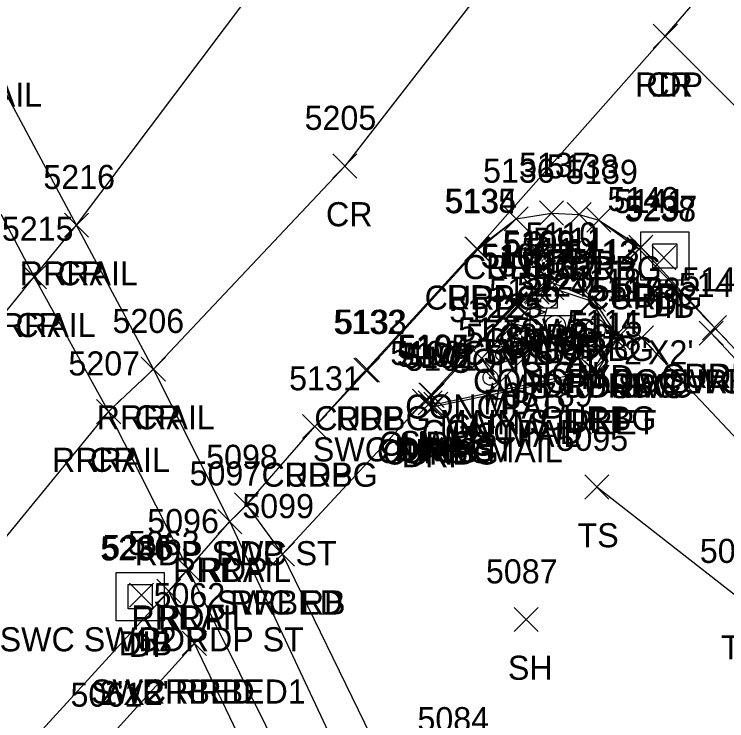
# Model space of a CAD drawing. Extents: x 1618146 to 1620418, y 640749 to 641927.
# Drawn here: x 1620288.8 to 1620347.9, y 640931.1 to 640989.8 of the extents above; entities that cross this region are included whole.
import ezdxf

# ---------------------------------------------------------------- set-up
doc = ezdxf.new("R2010")
doc.units = 0
for name, color, linetype in [('D_A', 7, 'Continuous'), ('D_C', 7, 'Continuous'), ('D_I', 7, 'Continuous'), ('D_TIC', 7, 'Continuous'), ('DS', 7, 'Continuous'), ('L_A', 7, 'Continuous'), ('L_C', 7, 'Continuous'), ('L_I', 7, 'Continuous'), ('L_TIC', 7, 'Continuous'), ('LELB', 7, 'Continuous'), ('LMB', 7, 'Continuous'), ('LS', 7, 'Continuous'), ('P_A', 7, 'Continuous'), ('P_I', 7, 'Continuous'), ('P_TIC', 7, 'Continuous'), ('PET', 7, 'Continuous'), ('PRC', 7, 'Continuous'), ('R_A', 7, 'Continuous'), ('R_I', 7, 'Continuous'), ('R_TIC', 7, 'Continuous'), ('RC', 7, 'Continuous'), ('RDP', 7, 'Continuous'), ('RR', 7, 'Continuous'), ('RRB', 7, 'Continuous'), ('RSW', 7, 'Continuous'), ('S_A', 7, 'Continuous'), ('S_C', 7, 'Continuous'), ('S_I', 7, 'Continuous'), ('SSGN', 7, 'Continuous'), ('U_A', 7, 'Continuous'), ('U_C', 7, 'Continuous'), ('U_I', 7, 'Continuous'), ('UP', 7, 'Continuous'), ('UPGW', 7, 'Continuous'), ('UWFH', 7, 'Continuous')]:
    doc.layers.add(name, color=color, linetype=linetype)

msp = doc.modelspace()

# ---------------------------------------------------------------- linework, layer by layer
at = {"layer": 'D_TIC'}
for points in [[(1620341.709, 640968.564), (1620343.709, 640970.564)], [(1620343.709, 640968.564), (1620341.709, 640970.564)], [(1620298.337, 640940.546), (1620300.337, 640942.546)], [(1620300.337, 640940.546), (1620298.337, 640942.546)]]:
    msp.add_lwpolyline(points, dxfattribs=at)
at = {"layer": 'DS'}
for p, q in [((1620340.801, 640971.698), (1620344.801, 640971.698)), ((1620340.801, 640967.698), (1620340.801, 640971.698)), ((1620344.801, 640971.698), (1620344.801, 640967.698)), ((1620341.801, 640968.698), (1620341.801, 640970.698)), ((1620341.801, 640970.698), (1620343.801, 640970.698)), ((1620343.801, 640970.698), (1620343.801, 640968.698)), ((1620342.806, 640969.699), (1620342.806, 640969.699)), ((1620342.806, 640969.699), (1620342.806, 640969.699)), ((1620343.801, 640968.698), (1620341.801, 640968.698)), ((1620344.801, 640967.698), (1620340.801, 640967.698)), ((1620297.224, 640943.429), (1620301.224, 640943.429)), ((1620297.224, 640939.429), (1620297.224, 640943.429)), ((1620301.224, 640943.429), (1620301.224, 640939.429)), ((1620298.224, 640940.429), (1620298.224, 640942.429)), ((1620298.224, 640942.429), (1620300.224, 640942.429)), ((1620300.224, 640942.429), (1620300.224, 640940.429)), ((1620299.229, 640941.431), (1620299.229, 640941.431)), ((1620299.229, 640941.431), (1620299.229, 640941.431)), ((1620300.224, 640940.429), (1620298.224, 640940.429)), ((1620301.224, 640939.429), (1620297.224, 640939.429))]:
    msp.add_line(p, q, dxfattribs=at)
at = {"layer": 'L_TIC'}
for points in [[(1620330.186, 640964), (1620332.186, 640966)], [(1620332.186, 640964), (1620330.186, 640966)], [(1620330.186, 640964), (1620332.186, 640966)], [(1620332.186, 640964), (1620330.186, 640966)], [(1620332.227, 640962.328), (1620334.227, 640964.328)], [(1620334.227, 640962.328), (1620332.227, 640964.328)], [(1620332.227, 640962.328), (1620334.227, 640964.328)], [(1620334.227, 640962.328), (1620332.227, 640964.328)], [(1620326.589, 640960.206), (1620328.589, 640962.206)], [(1620328.589, 640960.206), (1620326.589, 640962.206)], [(1620327.968, 640958.086), (1620329.968, 640960.086)], [(1620329.968, 640958.086), (1620327.968, 640960.086)], [(1620336.144, 640949.526), (1620338.144, 640951.526)], [(1620338.144, 640949.526), (1620336.144, 640951.526)], [(1620330.281, 640938.527), (1620332.281, 640940.527)], [(1620332.281, 640938.527), (1620330.281, 640940.527)]]:
    msp.add_lwpolyline(points, dxfattribs=at)
at = {"layer": 'LELB'}
msp.add_lwpolyline([(1620363.762, 640926.588), (1620349.048, 640941.226), (1620337.144, 640950.526)], dxfattribs=at)
at = {"layer": 'LMB'}
for p, q in [((1620331.61, 640965.461), (1620332.904, 640965.079)), ((1620331.616, 640962.869), (1620331.615, 640965.463)), ((1620331.615, 640964.562), (1620332.898, 640965.07)), ((1620330.06, 640964.166), (1620331.354, 640963.784)), ((1620330.066, 640961.573), (1620330.065, 640964.168)), ((1620330.065, 640963.266), (1620331.347, 640963.775)), ((1620330.96, 640962.86), (1620330.96, 640962.86)), ((1620329.41, 640961.565), (1620329.41, 640961.565))]:
    msp.add_line(p, q, dxfattribs=at)
for centre in [(1620330.96, 640962.86), (1620329.41, 640961.565)]:
    msp.add_circle(centre, 0.656, dxfattribs=at)
at = {"layer": 'LS'}
for points in [[(1620331.186, 640965), (1620327.589, 640961.206), (1620328.968, 640959.086), (1620333.227, 640963.328)], [(1620331.186, 640965), (1620333.227, 640963.328)]]:
    msp.add_lwpolyline(points, dxfattribs=at)
at = {"layer": 'P_TIC'}
for points in [[(1620341.84, 640986.934), (1620343.84, 640988.934)], [(1620343.84, 640986.934), (1620341.84, 640988.934)], [(1620341.84, 640986.934), (1620343.84, 640988.934)], [(1620343.84, 640986.934), (1620341.84, 640988.934)], [(1620315.225, 640976.168), (1620317.225, 640978.168)], [(1620317.225, 640976.168), (1620315.225, 640978.168)], [(1620332.388, 640972.265), (1620334.388, 640974.265)], [(1620334.388, 640972.265), (1620332.388, 640974.265)], [(1620329.453, 640971.78), (1620331.453, 640973.78)], [(1620331.453, 640971.78), (1620329.453, 640973.78)], [(1620334.685, 640972.14), (1620336.685, 640974.14)], [(1620336.685, 640972.14), (1620334.685, 640974.14)], [(1620336.312, 640971.687), (1620338.312, 640973.687)], [(1620338.312, 640971.687), (1620336.312, 640973.687)], [(1620292.935, 640971.261), (1620294.935, 640973.261)], [(1620294.935, 640971.261), (1620292.935, 640973.261)], [(1620326.197, 640969.287), (1620328.197, 640971.287)], [(1620328.197, 640969.287), (1620326.197, 640971.287)], [(1620326.197, 640969.287), (1620328.197, 640971.287)], [(1620328.197, 640969.287), (1620326.197, 640971.287)], [(1620339.814, 640969.424), (1620341.814, 640971.424)], [(1620341.814, 640969.424), (1620339.814, 640971.424)], [(1620289.437, 640966.965), (1620291.437, 640968.965)], [(1620291.437, 640966.965), (1620289.437, 640968.965)], [(1620345.935, 640962.754), (1620347.935, 640964.754)], [(1620347.935, 640962.754), (1620345.935, 640964.754)], [(1620299.323, 640959.311), (1620301.323, 640961.311)], [(1620301.323, 640959.311), (1620299.323, 640961.311)], [(1620316.973, 640959.228), (1620318.973, 640961.228)], [(1620318.973, 640959.228), (1620316.973, 640961.228)], [(1620295.609, 640955.784), (1620297.609, 640957.784)], [(1620297.609, 640955.784), (1620295.609, 640957.784)], [(1620312.723, 640954.551), (1620314.723, 640956.551)], [(1620314.723, 640954.551), (1620312.723, 640956.551)], [(1620307.049, 640948.035), (1620309.049, 640950.035)], [(1620309.049, 640948.035), (1620307.049, 640950.035)], [(1620305.673, 640946.652), (1620307.673, 640948.652)], [(1620307.673, 640946.652), (1620305.673, 640948.652)], [(1620302.215, 640942.7), (1620304.215, 640944.7)], [(1620304.215, 640942.7), (1620302.215, 640944.7)], [(1620300.599, 640940.889), (1620302.599, 640942.889)], [(1620302.599, 640940.889), (1620300.599, 640942.889)]]:
    msp.add_lwpolyline(points, dxfattribs=at)
at = {"layer": 'PET'}
for points in [[(1620301.599, 640941.889), (1620306.673, 640947.652), (1620308.049, 640949.035), (1620313.723, 640955.551), (1620317.973, 640960.228), (1620327.197, 640970.287), (1620342.84, 640987.934), (1620349.43, 640995.592), (1620362.743, 641013.622), (1620363.905, 641016.91), (1620366.737, 641021.043), (1620371.936, 641023.376), (1620397.595, 641061.893), (1620399.294, 641063.904)], [(1620327.197, 640970.287), (1620330.453, 640972.78), (1620333.388, 640973.265), (1620335.685, 640973.14), (1620337.312, 640972.687), (1620340.814, 640970.424), (1620346.935, 640963.754), (1620367.542, 640941.861), (1620373.703, 640935.835)]]:
    msp.add_lwpolyline(points, dxfattribs=at)
at = {"layer": 'PRC'}
for points in [[(1620224.798, 640884.187), (1620252.423, 640919.672), (1620271.906, 640945.144), (1620290.437, 640967.965), (1620293.935, 640972.261), (1620320.636, 641007.736), (1620341.521, 641037.703), (1620358.234, 641062.028), (1620372.9, 641083.065)], [(1620386.404, 641071.706), (1620361.021, 641035.235), (1620336.241, 641002.906), (1620316.225, 640977.168), (1620300.323, 640960.311), (1620296.609, 640956.784), (1620272.862, 640927.85), (1620252.181, 640901.579), (1620233.904, 640877.595)], [(1620383.892, 640943.083), (1620360.588, 640970.148), (1620342.84, 640987.934)]]:
    msp.add_lwpolyline(points, dxfattribs=at)
at = {"layer": 'R_TIC'}
for points in [[(1620329.453, 640971.78), (1620331.453, 640973.78)], [(1620331.453, 640971.78), (1620329.453, 640973.78)], [(1620336.312, 640971.687), (1620338.312, 640973.687)], [(1620338.312, 640971.687), (1620336.312, 640973.687)], [(1620292.935, 640971.261), (1620294.935, 640973.261)], [(1620294.935, 640971.261), (1620292.935, 640973.261)], [(1620326.272, 640969.247), (1620328.272, 640971.247)], [(1620328.272, 640969.247), (1620326.272, 640971.247)], [(1620339.677, 640969.265), (1620341.677, 640971.265)], [(1620341.677, 640969.265), (1620339.677, 640971.265)], [(1620289.437, 640966.965), (1620291.437, 640968.965)], [(1620291.437, 640966.965), (1620289.437, 640968.965)], [(1620332.444, 640966.497), (1620334.444, 640968.497)], [(1620334.444, 640966.497), (1620332.444, 640968.497)], [(1620331.114, 640965.823), (1620333.114, 640967.823)], [(1620333.114, 640965.823), (1620331.114, 640967.823)], [(1620331.192, 640965.699), (1620333.192, 640967.699)], [(1620333.192, 640965.699), (1620331.192, 640967.699)], [(1620332.422, 640966.06), (1620334.422, 640968.06)], [(1620334.422, 640966.06), (1620332.422, 640968.06)], [(1620335.861, 640965.101), (1620337.861, 640967.101)], [(1620337.861, 640965.101), (1620335.861, 640967.101)], [(1620329.338, 640964.737), (1620331.338, 640966.737)], [(1620331.338, 640964.737), (1620329.338, 640966.737)], [(1620329.39, 640964.654), (1620331.39, 640966.654)], [(1620331.39, 640964.654), (1620329.39, 640966.654)], [(1620335.656, 640964.98), (1620337.656, 640966.98)], [(1620337.656, 640964.98), (1620335.656, 640966.98)], [(1620345.935, 640962.754), (1620347.935, 640964.754)], [(1620347.935, 640962.754), (1620345.935, 640964.754)], [(1620345.649, 640962.3), (1620347.649, 640964.3)], [(1620347.649, 640962.3), (1620345.649, 640964.3)], [(1620345.649, 640962.3), (1620347.649, 640964.3)], [(1620347.649, 640962.3), (1620345.649, 640964.3)], [(1620337.601, 640961.951), (1620339.601, 640963.951)], [(1620339.601, 640961.951), (1620337.601, 640963.951)], [(1620337.601, 640961.951), (1620339.601, 640963.951)], [(1620339.601, 640961.951), (1620337.601, 640963.951)], [(1620337.928, 640961.949), (1620339.928, 640963.949)], [(1620339.928, 640961.949), (1620337.928, 640963.949)], [(1620337.928, 640961.949), (1620339.928, 640963.949)], [(1620339.928, 640961.949), (1620337.928, 640963.949)], [(1620339.868, 640961.901), (1620341.868, 640963.901)], [(1620341.868, 640961.901), (1620339.868, 640963.901)], [(1620299.323, 640959.311), (1620301.323, 640961.311)], [(1620301.323, 640959.311), (1620299.323, 640961.311)], [(1620317.109, 640959.236), (1620319.109, 640961.236)], [(1620319.109, 640959.236), (1620317.109, 640961.236)], [(1620335.851, 640959.222), (1620337.851, 640961.222)], [(1620337.851, 640959.222), (1620335.851, 640961.222)], [(1620336.116, 640958.999), (1620338.116, 640960.999)], [(1620338.116, 640958.999), (1620336.116, 640960.999)], [(1620322.38, 640957.179), (1620324.38, 640959.179)], [(1620324.38, 640957.179), (1620322.38, 640959.179)], [(1620322.482, 640957.123), (1620324.482, 640959.123)], [(1620324.482, 640957.123), (1620322.482, 640959.123)], [(1620321.854, 640956.653), (1620323.854, 640958.653)], [(1620323.854, 640956.653), (1620321.854, 640958.653)], [(1620321.854, 640956.653), (1620323.854, 640958.653)], [(1620323.854, 640956.653), (1620321.854, 640958.653)], [(1620322.315, 640956.504), (1620324.315, 640958.504)], [(1620324.315, 640956.504), (1620322.315, 640958.504)], [(1620322.773, 640956.392), (1620324.773, 640958.392)], [(1620324.773, 640956.392), (1620322.773, 640958.392)], [(1620322.773, 640956.392), (1620324.773, 640958.392)], [(1620324.773, 640956.392), (1620322.773, 640958.392)], [(1620295.609, 640955.784), (1620297.609, 640957.784)], [(1620297.609, 640955.784), (1620295.609, 640957.784)], [(1620322.472, 640956.173), (1620324.472, 640958.173)], [(1620324.472, 640956.173), (1620322.472, 640958.173)], [(1620312.723, 640954.551), (1620314.723, 640956.551)], [(1620314.723, 640954.551), (1620312.723, 640956.551)], [(1620307.049, 640948.035), (1620309.049, 640950.035)], [(1620309.049, 640948.035), (1620307.049, 640950.035)], [(1620305.673, 640946.652), (1620307.673, 640948.652)], [(1620307.673, 640946.652), (1620305.673, 640948.652)], [(1620310.058, 640943.945), (1620312.058, 640945.945)], [(1620312.058, 640943.945), (1620310.058, 640945.945)], [(1620310.058, 640943.945), (1620312.058, 640945.945)], [(1620312.058, 640943.945), (1620310.058, 640945.945)], [(1620302.215, 640942.7), (1620304.215, 640944.7)], [(1620304.215, 640942.7), (1620302.215, 640944.7)], [(1620300.599, 640940.889), (1620302.599, 640942.889)], [(1620302.599, 640940.889), (1620300.599, 640942.889)], [(1620300.599, 640940.889), (1620302.599, 640942.889)], [(1620302.599, 640940.889), (1620300.599, 640942.889)], [(1620302.727, 640936.553), (1620304.727, 640938.553)], [(1620304.727, 640936.553), (1620302.727, 640938.553)], [(1620302.727, 640936.553), (1620304.727, 640938.553)], [(1620304.727, 640936.553), (1620302.727, 640938.553)]]:
    msp.add_lwpolyline(points, dxfattribs=at)
at = {"layer": 'RC'}
for points in [[(1620313.723, 640955.551), (1620318.109, 640960.236), (1620327.272, 640970.247), (1620330.453, 640972.78)], [(1620337.312, 640972.687), (1620340.677, 640970.265), (1620346.935, 640963.754), (1620346.649, 640963.3)], [(1620323.773, 640957.392), (1620323.315, 640957.504), (1620323.482, 640958.123), (1620330.39, 640965.654), (1620332.192, 640966.699), (1620333.422, 640967.06), (1620336.656, 640965.98), (1620338.601, 640962.951)], [(1620323.773, 640957.392), (1620336.851, 640960.222), (1620338.601, 640962.951)]]:
    msp.add_lwpolyline(points, dxfattribs=at)
at = {"layer": 'RDP'}
msp.add_lwpolyline([(1620322.854, 640957.653), (1620323.472, 640957.173), (1620337.116, 640959.999), (1620338.928, 640962.949)], dxfattribs=at)
at = {"layer": 'RR'}
for points in [[(1620346.466, 640860.448), (1620330.756, 640897.472), (1620318, 640923.549), (1620306.673, 640947.652), (1620300.323, 640960.311), (1620293.935, 640972.261), (1620285.981, 640987.098), (1620281.456, 640995.25), (1620258.355, 641033.113), (1620241.318, 641059.633), (1620217.616, 641094.164), (1620201.563, 641115.97), (1620192.149, 641127.788), (1620168.312, 641155.994)], [(1620341.494, 640859.435), (1620326.199, 640895.398), (1620313.957, 640922.099), (1620303.215, 640943.7), (1620296.609, 640956.784), (1620290.437, 640967.965), (1620282.921, 640982.142), (1620278.195, 640990.782), (1620254.107, 641030.531), (1620237.651, 641056.889), (1620213.711, 641091.105), (1620198.15, 641113.288), (1620190.752, 641121.585), (1620164.758, 641152.663)]]:
    msp.add_lwpolyline(points, dxfattribs=at)
at = {"layer": 'RRB'}
for points in [[(1620350.399, 640862.151), (1620333.696, 640898.491), (1620311.058, 640944.945)], [(1620337.907, 640859.107), (1620325.201, 640892.825), (1620303.727, 640937.553)]]:
    msp.add_lwpolyline(points, dxfattribs=at)
at = {"layer": 'RSW'}
for points in [[(1620308.049, 640949.035), (1620311.058, 640944.945), (1620322.854, 640957.653), (1620323.38, 640958.179), (1620330.338, 640965.737), (1620332.114, 640966.823), (1620333.444, 640967.497), (1620336.861, 640966.101), (1620338.928, 640962.949), (1620340.868, 640962.901), (1620360.507, 640942.056), (1620369.968, 640932.443)], [(1620346.649, 640963.3), (1620367.05, 640941.513)], [(1620246.621, 640868.861), (1620275.079, 640905.51), (1620286.747, 640918.928), (1620290.412, 640922.708), (1620296.264, 640929.294), (1620303.727, 640937.553), (1620301.599, 640941.889)], [(1620286.98, 640925.917), (1620301.599, 640941.889)]]:
    msp.add_lwpolyline(points, dxfattribs=at)
at = {"layer": 'SSGN'}
for p, q in [((1620332.064, 640964.763), (1620335.397, 640964.763)), ((1620333.711, 640963.93), (1620333.711, 640963.93))]:
    msp.add_line(p, q, dxfattribs=at)
msp.add_circle((1620333.711, 640963.93), 0.833, dxfattribs=at)
at = {"layer": 'UP'}
for p, q in [((1620333.267, 640967.858), (1620333.017, 640967.025)), ((1620332.183, 640965.358), (1620332.183, 640967.025)), ((1620332.183, 640967.025), (1620333.85, 640967.025)), ((1620333.85, 640967.025), (1620333.85, 640965.358)), ((1620333.017, 640966.191), (1620333.017, 640966.191)), ((1620333.85, 640965.358), (1620332.183, 640965.358)), ((1620332.767, 640964.525), (1620333.017, 640965.358))]:
    msp.add_line(p, q, dxfattribs=at)
msp.add_circle((1620333.017, 640966.191), 0.833, dxfattribs=at)
at = {"layer": 'UPGW'}
for radius in [0.625, 0.0833]:
    msp.add_circle((1620328.326, 640959.601), radius, dxfattribs=at)
at = {"layer": 'UWFH'}
msp.add_line((1620337.039, 640963.65), (1620337.039, 640963.65), dxfattribs=at)
for centre, radius in [((1620337.039, 640963.65), 0.833), ((1620336.039, 640963.65), 0.167), ((1620338.039, 640963.65), 0.167), ((1620337.039, 640962.65), 0.167)]:
    msp.add_circle(centre, radius, dxfattribs=at)

# ---------------------------------------------------------------- texts
at = {"layer": 'D_A'}
for s, p in [('DIB', (1620340.812, 640964.564)), ('DI', (1620341.861, 640964.699)), ('DIB', (1620297.44, 640936.546)), ('DI', (1620298.284, 640936.431))]:
    msp.add_text(s, height=2, dxfattribs=at).set_placement(p)
at = {"layer": 'D_C'}
for p in [(1620339.405, 640960.699), (1620295.827, 640932.431)]:
    msp.add_text("2'X2'", height=2, dxfattribs=at).set_placement(p)
at = {"layer": 'D_I'}
for s, p in [('5238', (1620339.45, 640972.564)), ('5237', (1620339.546, 640972.699)), ('5236', (1620295.914, 640944.431)), ('5235', (1620296.078, 640944.546))]:
    msp.add_text(s, height=2, dxfattribs=at).set_placement(p)
at = {"layer": 'L_A'}
for s, p in [('CONCPAD', (1620324.832, 640960)), ('CONCPAD', (1620324.832, 640960)), ('CONCPAD', (1620326.872, 640958.328)), ('CONCPAD', (1620326.872, 640958.328)), ('MB', (1620329.267, 640957.86)), ('CONCPAD', (1620321.234, 640956.206)), ('MB', (1620327.717, 640956.565)), ('CONCPAD', (1620322.614, 640954.086)), ('TS', (1620335.553, 640945.526)), ('TS', (1620347.457, 640936.226)), ('SH', (1620329.769, 640934.527))]:
    msp.add_text(s, height=2, dxfattribs=at).set_placement(p)
at = {"layer": 'L_C'}
for p in [(1620325.165, 640953.86), (1620323.615, 640952.565)]:
    msp.add_text('US MAIL', height=2, dxfattribs=at).set_placement(p)
at = {"layer": 'L_I'}
for s, p in [('5121', (1620329.061, 640968)), ('5121', (1620329.061, 640968)), ('5124', (1620330.534, 640966.328)), ('5124', (1620330.534, 640966.328)), ('5126', (1620328.212, 640965.86)), ('5125', (1620326.717, 640964.565)), ('5122', (1620324.896, 640964.206)), ('5123', (1620326.276, 640962.086)), ('5095', (1620333.805, 640953.526)), ('5094', (1620345.709, 640944.226)), ('5087', (1620327.943, 640942.527)), ('5061', (1620293.445, 640932.294)), ('5084', (1620322.257, 640930.259))]:
    msp.add_text(s, height=2, dxfattribs=at).set_placement(p)
at = {"layer": 'P_A'}
for s, p in [('RDP', (1620340.328, 640982.934)), ('CR', (1620341.273, 640982.934)), ('CR', (1620314.658, 640972.168)), ('RDP', (1620330.876, 640968.265)), ('RDP', (1620333.173, 640968.14)), ('RDP', (1620327.941, 640967.78)), ('RDP', (1620334.8, 640967.687)), ('CR', (1620292.368, 640967.261)), ('RDP', (1620324.685, 640965.287)), ('RDP', (1620324.685, 640965.287)), ('RDP', (1620338.302, 640965.424)), ('CR', (1620288.87, 640962.965)), ('RDP', (1620344.424, 640958.754)), ('CR', (1620298.756, 640955.311)), ('RDP', (1620315.461, 640955.228)), ('CR', (1620295.042, 640951.784)), ('RDP', (1620311.211, 640950.551)), ('RDP', (1620305.537, 640944.035)), ('RDP', (1620304.161, 640942.652)), ('RDP', (1620300.703, 640938.7)), ('RDP', (1620299.087, 640936.889))]:
    msp.add_text(s, height=2, dxfattribs=at).set_placement(p)
at = {"layer": 'P_I'}
for s, p in [('5205', (1620312.886, 640980.168)), ('5136', (1620327.705, 640975.78)), ('5137', (1620330.695, 640976.265)), ('5138', (1620332.993, 640976.14)), ('5216', (1620291.188, 640975.261)), ('5139', (1620334.611, 640975.687)), ('5140', (1620338.035, 640973.424)), ('5135', (1620324.504, 640973.287)), ('5135', (1620324.504, 640973.287)), ('5215', (1620287.744, 640970.965)), ('5142', (1620344.243, 640966.754)), ('5206', (1620296.93, 640963.311)), ('5132', (1620315.28, 640963.228)), ('5207', (1620293.271, 640959.784)), ('5131', (1620311.597, 640958.551)), ('5098', (1620304.71, 640952.035)), ('5097', (1620303.334, 640950.652)), ('5096', (1620299.821, 640946.7)), ('5063', (1620298.213, 640944.889))]:
    msp.add_text(s, height=2, dxfattribs=at).set_placement(p)
at = {"layer": 'R_A'}
for s, p in [('RRRAIL', (1620281.272, 640982.098)), ('CURBG', (1620326.036, 640967.78)), ('CURBG', (1620332.895, 640967.687)), ('RRRAIL', (1620289.227, 640967.261)), ('CURBG', (1620322.855, 640965.247)), ('CURBG', (1620336.26, 640965.265)), ('RRRAIL', (1620285.728, 640962.965)), ('SWC', (1620330.806, 640962.497)), ('CURBG', (1620327.774, 640961.699)), ('CURBG', (1620329.004, 640962.06)), ('SWC', (1620329.476, 640961.823)), ('CURBG', (1620332.239, 640960.98)), ('SWC', (1620334.223, 640961.101)), ('CURBG', (1620325.973, 640960.654)), ('SWC', (1620327.7, 640960.737)), ('CURBG', (1620342.518, 640958.754)), ('DRP SWC', (1620332.511, 640957.949)), ('CURBG', (1620334.184, 640957.951)), ('CURBG', (1620334.184, 640957.951)), ('CG SWC ST', (1620338.311, 640958.3)), ('CURBG', (1620342.232, 640958.3)), ('DRP', (1620336.417, 640957.949)), ('SWC', (1620338.231, 640957.901)), ('RRRAIL', (1620295.615, 640955.311)), ('CURBG', (1620313.692, 640955.236)), ('CURBG', (1620332.434, 640955.222)), ('DRP', (1620334.604, 640954.999)), ('SWC DRP ST', (1620313.571, 640952.653)), ('CURBG', (1620319.064, 640953.123)), ('DRP', (1620320.343, 640952.653)), ('SWC', (1620320.742, 640953.179)), ('CURBG', (1620318.898, 640952.504)), ('CURBG', (1620319.356, 640952.392)), ('CURBG', (1620319.356, 640952.392)), ('DRP', (1620320.96, 640952.173)), ('RRRAIL', (1620291.901, 640951.784)), ('CURBG', (1620309.305, 640950.551)), ('RDP SWC ST', (1620298.765, 640944.035)), ('RRRAIL', (1620301.964, 640942.652)), ('SWC RB', (1620305.585, 640939.945)), ('RRBED', (1620306.703, 640939.945)), ('RRRAIL', (1620298.506, 640938.7)), ('SWC SWC2 RDP ST', (1620287.559, 640936.889)), ('SWC SWC2 RDP ST', (1620287.559, 640936.889)), ('SWC RRBED1', (1620295.144, 640932.553)), ('RRBED', (1620299.373, 640932.553))]:
    msp.add_text(s, height=2, dxfattribs=at).set_placement(p)
at = {"layer": 'R_I'}
for s, p in [('5136', (1620327.705, 640975.78)), ('5216', (1620291.188, 640975.261)), ('5139', (1620334.611, 640975.687)), ('5134', (1620324.579, 640973.247)), ('5141', (1620338.552, 640973.265)), ('5215', (1620287.744, 640970.965)), ('5110', (1620331.232, 640970.497)), ('5109', (1620329.335, 640969.823)), ('5111', (1620331.863, 640970.06)), ('5108', (1620329.42, 640969.699)), ('5106', (1620327.511, 640968.737)), ('5107', (1620327.619, 640968.654)), ('5112', (1620334.531, 640968.98)), ('5113', (1620334.735, 640969.101)), ('5143', (1620343.957, 640966.3)), ('5143', (1620343.957, 640966.3)), ('5142', (1620344.243, 640966.754)), ('5117', (1620336.476, 640965.951)), ('5117', (1620336.476, 640965.951)), ('5116', (1620336.748, 640965.949)), ('5116', (1620336.748, 640965.949)), ('5128', (1620338.176, 640965.901)), ('5206', (1620296.93, 640963.311)), ('5133', (1620315.416, 640963.236)), ('5114', (1620334.725, 640963.222)), ('5115', (1620334.99, 640962.999)), ('5105', (1620320.608, 640961.179)), ('5104', (1620320.71, 640961.123)), ('5100', (1620319.996, 640960.653)), ('5100', (1620319.996, 640960.653)), ('5103', (1620320.544, 640960.504)), ('5102', (1620321.002, 640960.392)), ('5102', (1620321.002, 640960.392)), ('5207', (1620293.271, 640959.784)), ('5101', (1620321.267, 640960.173)), ('5131', (1620311.597, 640958.551)), ('5098', (1620304.71, 640952.035)), ('5097', (1620303.334, 640950.652)), ('5099', (1620307.711, 640947.945)), ('5099', (1620307.711, 640947.945)), ('5096', (1620299.821, 640946.7)), ('5063', (1620298.213, 640944.889)), ('5063', (1620298.213, 640944.889)), ('5062', (1620300.341, 640940.553)), ('5062', (1620300.341, 640940.553)), ('5061', (1620293.445, 640932.294))]:
    msp.add_text(s, height=2, dxfattribs=at).set_placement(p)
at = {"layer": 'S_A'}
msp.add_text('SIGN', height=2, dxfattribs=at).set_placement((1620330.849, 640958.909))
at = {"layer": 'S_C'}
msp.add_text('MAIN STREET', height=2, dxfattribs=at).set_placement((1620324.109, 640954.909))
at = {"layer": 'S_I'}
msp.add_text('5120', height=2, dxfattribs=at).set_placement((1620330.912, 640966.909))
at = {"layer": 'U_A'}
for s, p in [('COMB', (1620329.402, 640961.191)), ('HYD', (1620334.559, 640958.65)), ('GUYW', (1620324.719, 640954.601))]:
    msp.add_text(s, height=2, dxfattribs=at).set_placement(p)
at = {"layer": 'U_C'}
msp.add_text('#08789', height=2, dxfattribs=at).set_placement((1620327.875, 640957.191))
at = {"layer": 'U_I'}
for s, p in [('5119', (1620330.883, 640969.191)), ('5118', (1620334.913, 640966.65)), ('5127', (1620325.633, 640962.601))]:
    msp.add_text(s, height=2, dxfattribs=at).set_placement(p)

doc.saveas('drawing.dxf')
